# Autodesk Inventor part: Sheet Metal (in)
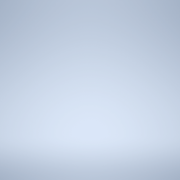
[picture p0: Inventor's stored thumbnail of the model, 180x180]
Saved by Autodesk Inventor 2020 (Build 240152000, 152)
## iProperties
Created: 2019-02
Part Number: Sheet Metal (in)
Material: Ogólny
Document SubType Name: Konstrukcja blachowa
Density: 1 g/cm^3
Sheet Metal Rule: Domyślny
Appearance: Domyślna
Catalog Web Link: www.expertbooks.pl
Designer: F.Stasiak
Manager: www.cadconsulting.pl
Company: Fabian Stasiak CAD Consulting
Subject: Zbiór ćwiczeń. Autodesk Inventor 2020. Kurs Professional
Author: F.Stasiak
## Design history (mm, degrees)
other parameters: "Grubość" = 3.048, "WspółczynnikK" = 4.4, "PromieńGięcia" = 3.048 (= Grubość), "SzerokośćGięciaPodcięcia" = 3.048 (= Grubość), "GłębokośćGięciaPodcięcia" = 1.524 (= 0.5 x Grubość), "RozmiarPodcięciaNarożnika" = 12.192 (= 4 x Grubość), "OdstępPołączenia" = 0.00508, "MinimalnaPozostałość" = 6.096 (= 2 x Grubość), "PromieńPrzejścia" = 3.048 (= PromieńGięcia), "Rozmiar_promienia_Jacobiego" = 3.048 (= Grubość), "Wielk_odstępu" = 3.048 (= Grubość)
